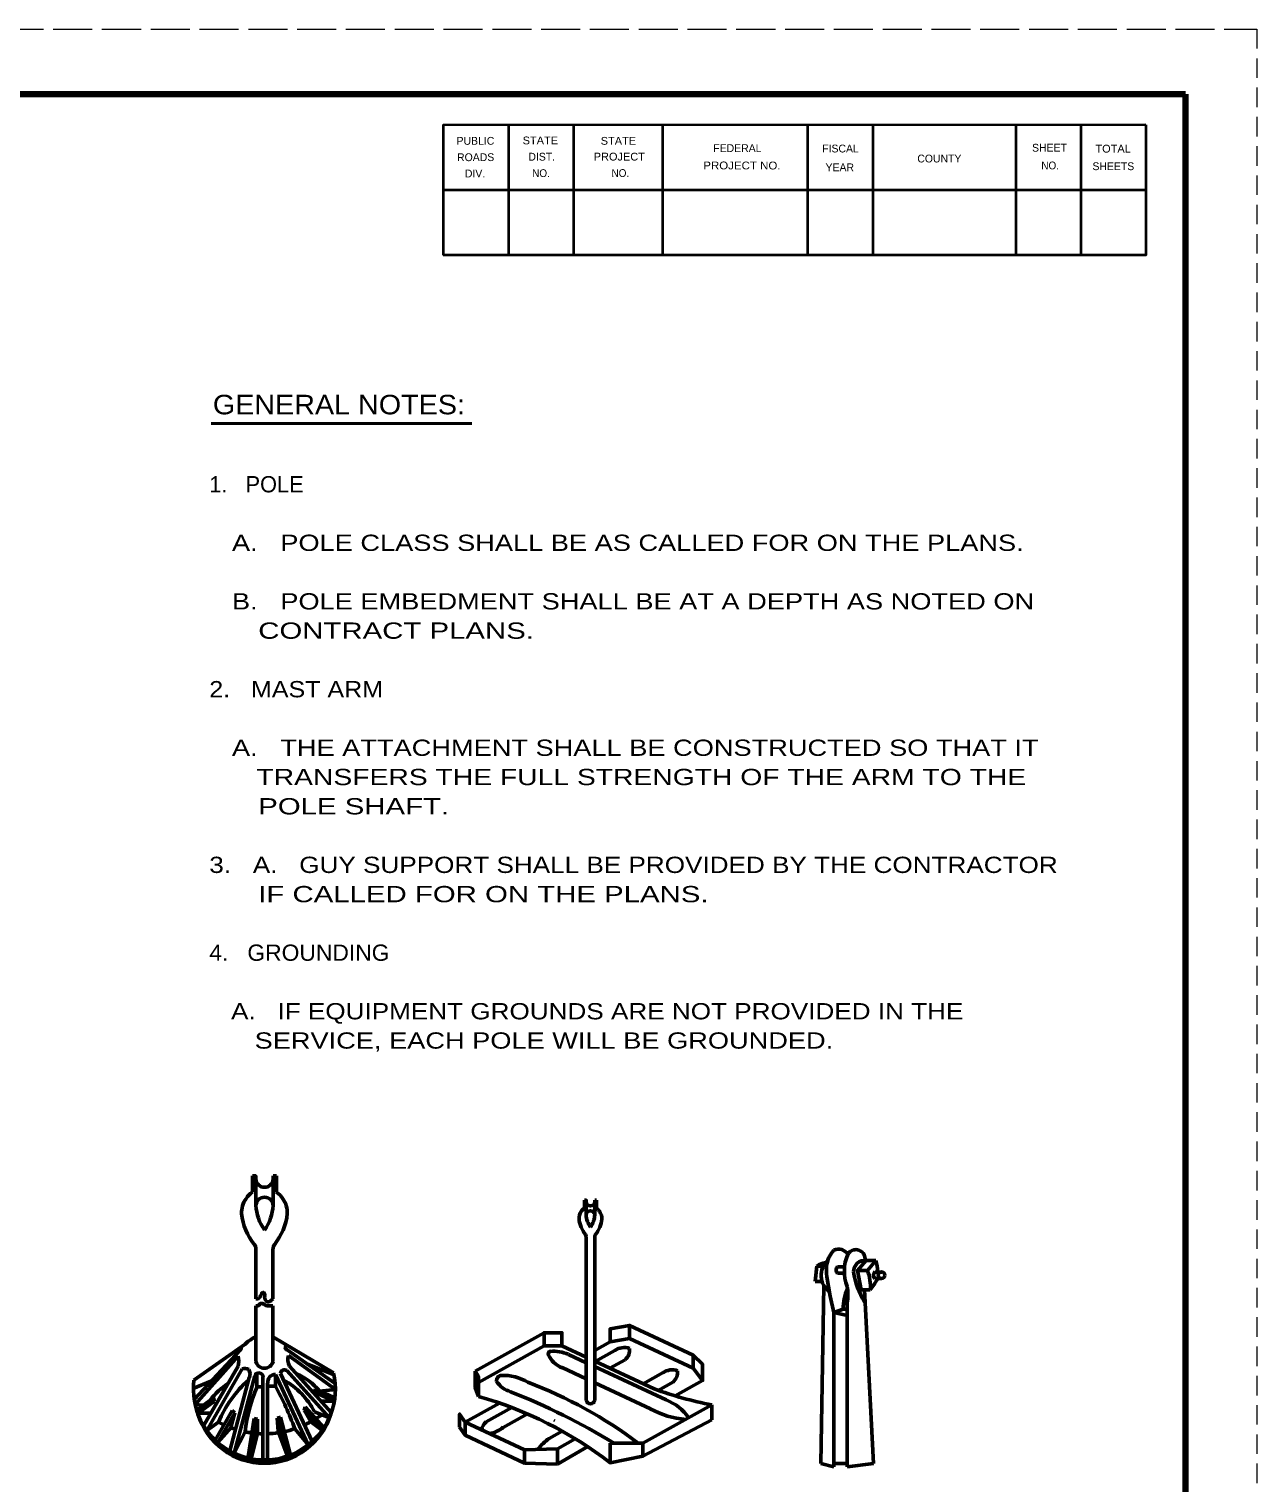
# Model space of a CAD drawing. Extents: x -1 to 679, y 0 to 440.
# Drawn here: x 490.2 to 678.9, y 216.8 to 440.2 of the extents above; entities that cross this region are included whole.
import ezdxf

# ---------------------------------------------------------------- set-up
doc = ezdxf.new("R2010")
doc.units = 0
doc.linetypes.add('LONG_DASHED', pattern=[7.5, 6, -1.5])
doc.linetypes.add('MEDIUM_DASHED', pattern=[4.5, 3, -1.5])
doc.layers.add('1', color=7, linetype='Continuous', lineweight=53)
doc.layers.add('61', color=7, linetype='Continuous', lineweight=35)

msp = doc.modelspace()

# ---------------------------------------------------------------- linework, layer by layer
at = {"layer": '1', "linetype": 'MEDIUM_DASHED', "lineweight": 13}
msp.add_line((678.891, 440.242), (678.871, 0.222), dxfattribs=at)
at = {"layer": '1', "lineweight": 40}
msp.add_line((518.16, 379.637), (558.213, 379.637), dxfattribs=at)
at = {"layer": '1'}
for p, q in [((524.516, 263.979), (524.516, 261.459)), ((527.676, 263.479), (527.676, 263.979)), ((527.676, 263.979), (528.176, 263.979)), ((528.176, 263.979), (528.176, 261.459)), ((525.016, 263.479), (525.016, 259.439)), ((527.676, 263.479), (527.676, 259.439)), ((575.536, 260.239), (575.536, 258.979)), ((575.796, 259.999), (575.796, 257.979)), ((577.116, 259.999), (577.116, 260.239)), ((577.116, 260.239), (577.376, 260.239)), ((577.116, 259.999), (577.116, 257.979)), ((577.376, 260.239), (577.376, 258.979)), ((525.016, 252.779), (525.016, 245.059)), ((527.656, 252.779), (527.656, 245.059)), ((575.796, 254.639), (575.796, 229.439)), ((577.116, 254.639), (577.116, 229.439)), ((611.236, 250.119), (610.996, 247.719)), ((612.256, 250.119), (611.236, 250.119)), ((615.516, 249.999), (614.416, 249.999)), ((615.436, 249.019), (614.416, 249.019)), ((621.216, 249.199), (620.196, 249.199)), ((621.216, 248.199), (620.196, 248.199)), ((611.996, 247.719), (610.996, 247.719)), ((611.856, 219.779), (612.336, 247.099)), ((618.556, 246.459), (618.056, 246.459)), ((619.956, 219.779), (618.556, 246.459)), ((618.556, 246.459), (619.456, 246.459)), ((525.016, 235.419), (525.016, 243.999)), ((527.656, 235.419), (527.656, 243.999)), ((615.896, 219.279), (615.896, 244.479)), ((613.876, 219.279), (613.876, 242.959)), ((613.876, 242.959), (615.896, 242.539)), ((527.636, 239.259), (536.956, 233.679)), ((569.316, 239.859), (558.736, 233.979)), ((582.436, 240.999), (592.256, 236.419)), ((523.376, 238.119), (515.496, 232.599)), ((522.656, 237.259), (515.536, 229.619)), ((529.836, 237.259), (537.216, 232.079)), ((569.316, 237.839), (559.236, 232.239)), ((572.076, 237.839), (575.776, 236.099)), ((579.456, 238.459), (577.116, 237.159)), ((580.196, 237.139), (577.176, 235.459)), ((579.456, 238.459), (582.436, 238.979)), ((582.436, 238.979), (592.256, 234.399)), ((522.296, 236.239), (515.676, 228.819)), ((522.296, 234.739), (516.996, 225.559)), ((530.016, 236.379), (537.256, 231.119)), ((530.196, 234.739), (536.616, 227.599)), ((536.956, 233.459), (532.976, 235.059)), ((573.056, 236.539), (575.796, 235.259)), ((577.096, 234.659), (588.076, 229.539)), ((577.116, 235.499), (586.236, 231.239)), ((581.796, 235.719), (579.436, 234.399)), ((592.256, 236.419), (592.256, 234.399)), ((522.936, 234.319), (517.476, 224.859)), ((524.016, 232.999), (520.996, 221.699)), ((524.876, 233.239), (521.676, 221.339)), ((525.196, 231.559), (525.196, 233.679)), ((526.116, 233.079), (526.116, 220.299)), ((528.056, 233.459), (533.076, 222.659)), ((528.816, 233.599), (533.696, 223.159)), ((529.796, 234.059), (536.316, 226.799)), ((572.096, 234.499), (575.796, 232.759)), ((587.636, 233.739), (584.536, 232.019)), ((515.396, 231.299), (518.116, 232.399)), ((525.196, 231.559), (526.116, 231.559)), ((526.836, 232.139), (526.836, 220.299)), ((534.156, 231.239), (537.016, 229.899)), ((534.156, 231.239), (534.176, 230.659)), ((534.176, 230.659), (536.996, 229.359)), ((537.256, 231.119), (534.856, 230.899)), ((577.116, 232.159), (585.656, 228.179)), ((589.196, 232.299), (586.856, 230.999)), ((515.676, 228.819), (516.916, 228.719)), ((515.836, 227.919), (518.496, 229.839)), ((516.136, 227.519), (518.656, 229.339)), ((518.496, 229.839), (518.656, 229.339)), ((532.616, 228.479), (532.436, 227.939)), ((532.436, 227.939), (535.096, 224.959)), ((533.456, 226.179), (532.436, 227.939)), ((532.616, 228.479), (535.476, 225.299)), ((536.996, 229.359), (535.036, 229.359)), ((564.376, 228.359), (560.396, 226.159)), ((595.096, 228.759), (595.096, 226.499)), ((516.136, 227.519), (518.176, 227.519)), ((517.476, 224.859), (519.296, 226.139)), ((518.776, 223.339), (521.396, 227.899)), ((519.156, 222.999), (521.776, 227.559)), ((521.776, 227.559), (521.196, 225.319)), ((521.396, 227.899), (521.776, 227.559)), ((524.776, 226.679), (523.836, 220.779)), ((525.256, 226.599), (524.336, 220.699)), ((524.776, 226.679), (525.256, 226.599)), ((525.256, 226.599), (525.256, 224.359)), ((528.796, 226.899), (528.296, 226.759)), ((528.296, 226.759), (529.836, 221.059)), ((528.296, 226.759), (528.476, 224.719)), ((528.796, 226.899), (530.296, 221.259)), ((535.096, 224.959), (533.456, 226.179)), ((536.316, 226.799), (534.056, 227.699)), ((557.196, 226.119), (566.336, 221.859)), ((557.196, 226.119), (557.196, 224.099)), ((566.756, 227.379), (563.056, 225.319)), ((519.156, 222.999), (521.216, 225.299)), ((521.676, 221.339), (523.356, 224.639)), ((524.336, 220.699), (525.256, 224.359)), ((529.836, 221.059), (528.476, 224.719)), ((533.076, 222.659), (531.016, 225.099)), ((572.096, 224.739), (570.116, 223.599)), ((574.096, 223.579), (571.396, 222.019)), ((566.336, 221.859), (571.376, 222.039)), ((566.336, 221.859), (566.336, 219.839)), ((576.056, 222.379), (571.376, 219.659)), ((571.376, 222.039), (571.376, 219.659)), ((584.516, 222.899), (584.516, 220.879)), ((566.336, 219.839), (571.376, 219.659)), ((611.856, 219.779), (613.876, 219.279)), ((613.876, 219.779), (615.896, 219.779)), ((615.896, 219.279), (619.956, 219.779))]:
    msp.add_line(p, q, dxfattribs=at)
at = {"layer": '1', "lineweight": 13}
for p, q in [((589.496, 230.159), (589.316, 230.059)), ((570.816, 226.219), (571.016, 226.559))]:
    msp.add_line(p, q, dxfattribs=at)
at = {"layer": '1'}
for points in [[(525.016, 263.479), (525.016, 263.979), (524.516, 263.979)], [(575.796, 259.999), (575.796, 260.239), (575.536, 260.239)], [(618.056, 246.459), (617.516, 249.439), (619.036, 249.439), (620.336, 250.979)], [(617.516, 249.439), (618.816, 250.979), (620.336, 250.979)], [(613.876, 242.959), (613.316, 245.479), (612.796, 248.459)], [(613.876, 242.959), (615.296, 243.479), (615.896, 243.479)], [(579.456, 238.459), (579.456, 240.459), (582.436, 240.999), (582.436, 238.979)], [(592.256, 235.999), (592.256, 236.419), (593.696, 235.019), (593.696, 232.499)], [(528.056, 233.459), (528.056, 231.639), (526.836, 231.639)], [(558.736, 233.979), (559.236, 233.119), (559.236, 230.079)], [(558.736, 233.979), (558.736, 231.459), (559.236, 230.079)], [(592.256, 234.399), (593.696, 232.499), (589.496, 230.159)], [(562.496, 229.059), (557.196, 226.119), (556.336, 227.359), (556.336, 225.339)], [(595.096, 228.759), (584.516, 222.899), (579.476, 222.899)], [(579.476, 222.899), (579.476, 219.879), (584.516, 220.879), (595.096, 226.499)], [(556.336, 225.339), (557.196, 224.099), (566.336, 219.839)]]:
    msp.add_lwpolyline(points, dxfattribs=at)
msp.add_lwpolyline([(572.076, 237.839), (572.076, 239.859), (569.316, 239.859), (569.316, 237.839)], close=True, dxfattribs=at)
msp.add_circle((621.191, 248.704), 0.504, dxfattribs=at)
for centre, radius, start, end in [((525.793, 259.176), 2.616, 119.19068, 150.80932), ((526.351, 263.548), 1.332, 183.14868, 356.60343), ((526.886, 259.176), 2.616, 29.19068, 60.80932), ((526.509, 258.307), 3.688, 144.42176, 182.06662), ((526.351, 259.364), 1.332, 3.15687, 176.59703), ((532.291, 259.869), 7.282, 183.35766, 215.34932), ((520.412, 259.864), 7.282, 324.65068, 356.64234), ((526.171, 258.307), 3.688, 357.93338, 35.57824), ((576.455, 260.031), 0.666, 183.14868, 356.60343), ((532.175, 259.25), 9.414, 186.56595, 218.44896), ((520.505, 259.25), 9.414, 321.55104, 353.43405), ((576.534, 257.41), 1.844, 144.42176, 182.06662), ((579.367, 257.882), 4.707, 186.56595, 218.44896), ((576.176, 257.845), 1.308, 119.19068, 150.80932), ((576.455, 257.939), 0.666, 3.15687, 176.59703), ((579.425, 258.192), 3.641, 183.35766, 215.34932), ((573.485, 258.189), 3.641, 324.65068, 356.64234), ((573.532, 257.882), 4.707, 321.55104, 353.43405), ((576.722, 257.845), 1.308, 29.19068, 60.80932), ((576.365, 257.41), 1.844, 357.93338, 35.57824), ((575.286, 254.642), 0.504, 0, 38.44896), ((577.612, 254.642), 0.504, 141.55104, 180), ((524.014, 252.77), 1.008, 0, 38.44896), ((528.666, 252.77), 1.008, 141.55104, 180), ((617.02, 249.568), 4.325, 136.6517, 167.95246), ((614.601, 251.124), 1.588, 27.27122, 117.20122), ((617.252, 251.212), 1.423, 354.19595, 131.52888), ((613.133, 247.234), 3.446, 98.89517, 123.27294), ((614.931, 248.656), 3.032, 130.0252, 235.18403), ((622.401, 249.463), 9.664, 174.01262, 185.98737), ((622.061, 249.306), 6.589, 156.78247, 200.56684), ((619.515, 249.365), 4.332, 137.75004, 144.12043), ((618.637, 249.241), 1.744, 84.04734, 179.89391), ((614.978, 249.361), 5.59, 358.55245, 16.7912), ((614.89, 249.511), 0.671, 133.97941, 226.02058), ((628.805, 250.931), 12.03, 188.05699, 211.90806), ((612.645, 246.995), 6.838, 355.44941, 20.86555), ((612.251, 252.251), 9.252, 321.19678, 333.99968), ((620.559, 248.699), 0.618, 125.33791, 234.66209), ((623.717, 243.391), 8.422, 157.16459, 179.40955), ((610.27, 245.733), 5.76, 347.36391, 12.63609), ((528.106, 233.103), 6.892, 116.58954, 133.41014), ((522.609, 237.411), 0.167, 285.47106, 119.84894), ((529.834, 237.548), 0.298, 72.34222, 272.05741), ((570.341, 236.624), 0.386, 85.12517, 207.35251), ((570.706, 230.949), 6.071, 67.29002, 93.88305), ((581.638, 235.092), 2.502, 70.73362, 125.44724), ((580.396, 237.257), 2.077, 312.2199, 5.43688), ((519.368, 235.486), 3.028, 345.54353, 14.45647), ((526.34, 235.785), 1.368, 195.24731, 344.75269), ((532.305, 235.796), 2.362, 165.83192, 206.84011), ((573.544, 238.143), 3.929, 204.55458, 248.28903), ((526.334, 231.225), 10.92, 172.76636, 12.86069), ((535.571, 219.45), 17.588, 131.72438, 157.64771), ((523.291, 232.954), 1.417, 63.18198, 104.27978), ((522.796, 233.516), 1.334, 336.72582, 31.75765), ((525.483, 233.051), 0.64, 2.53809, 163.55027), ((528.028, 232.26), 1.196, 89.05434, 186.28866), ((529.433, 233.544), 0.621, 54.79805, 174.78973), ((523.671, 222.377), 11.659, 27.13242, 61.23505), ((526.2, 223.113), 11.652, 41.97741, 64.76098), ((562.821, 232.507), 0.804, 94.88611, 188.90189), ((563.034, 225.968), 7.345, 59.08543, 92.19679), ((589.017, 231.665), 2.502, 70.73362, 125.44724), ((587.775, 233.83), 2.077, 312.2199, 5.43688), ((526.823, 222.711), 11.153, 122.96526, 142.37873), ((551.034, 220.963), 27.92, 157.68458, 172.42454), ((482.668, 207.115), 51.58, 20.41201, 28.38414), ((565.204, 234.448), 3.79, 213.03543, 254.05828), ((525.168, 132.459), 105.794, 58.74865, 68.37109), ((542.249, 167.701), 69.082, 53.04115, 69.17556), ((606.818, 288.061), 60.44, 250.09888, 258.8259), ((542.438, 171.585), 60.867, 52.50633, 73.9788), ((576.449, 229.621), 0.683, 195.19877, 344.80123), ((592.153, 239.974), 13.477, 241.1379, 265.46719), ((585.415, 222.67), 7.369, 33.93256, 68.86981), ((526.334, 230.48), 10.679, 196.98242, 343.01758), ((526.334, 238.953), 14.616, 241.25089, 244.7288), ((526.334, 238.953), 14.616, 294.68825, 298.86032), ((526.334, 238.953), 14.616, 302.79246, 306.95206), ((561.815, 224.509), 2.176, 130.48502, 167.67788), ((526.334, 238.953), 14.616, 249.43644, 252.21677), ((526.334, 238.953), 14.616, 258.07352, 262.19692), ((526.334, 238.953), 14.616, 265.78587, 269.16942), ((526.334, 238.953), 14.616, 271.8867, 278.3643), ((526.334, 238.953), 14.616, 282.12514, 288.50814), ((559.861, 229.343), 5.13, 282.65039, 308.50672), ((572.968, 218.907), 5.489, 121.25992, 146.56057)]:
    msp.add_arc(centre, radius, start, end, dxfattribs=at)
for points in [[(525.016, 245.059), (525.456, 245.139), (525.716, 245.519), (525.976, 245.959), (526.236, 246.039), (526.376, 245.619), (526.376, 245.259), (526.496, 244.919), (526.756, 244.619), (527.156, 244.659), (527.536, 244.999), (527.656, 245.059)], [(525.016, 243.999), (525.296, 243.999), (525.496, 244.099), (525.676, 244.339), (525.876, 244.379), (526.196, 244.299), (526.376, 244.139), (526.796, 243.999), (527.116, 243.999), (527.656, 243.999)]]:
    msp.add_spline(points, degree=3, dxfattribs=at)
at = {"layer": '61', "linetype": 'LONG_DASHED', "lineweight": 13}
msp.add_line((-1.129, 440.242), (678.891, 440.242), dxfattribs=at)
at = {"layer": '61', "lineweight": 158}
msp.add_line((667.911, 430.242), (667.931, 10.202), dxfattribs=at)
at = {"layer": '61'}
for p, q in [((563.831, 425.482), (563.831, 405.482)), ((573.831, 425.482), (573.831, 405.482)), ((587.511, 425.482), (587.511, 405.482)), ((609.831, 425.482), (609.831, 405.482)), ((619.831, 425.482), (619.831, 405.482)), ((641.811, 425.502), (641.811, 405.502)), ((651.811, 425.502), (651.811, 405.502)), ((661.831, 415.462), (553.811, 415.482))]:
    msp.add_line(p, q, dxfattribs=at)
at = {"layer": '61', "lineweight": 158}
msp.add_lwpolyline([(667.911, 430.242), (28.871, 430.242), (28.871, 10.222)], dxfattribs=at)
at = {"layer": '61'}
for points in [[(661.811, 425.502), (553.831, 425.482), (553.831, 405.482)], [(661.811, 425.502), (661.811, 405.502), (553.831, 405.482)]]:
    msp.add_lwpolyline(points, dxfattribs=at)

# ---------------------------------------------------------------- texts
at = {"layer": '1'}
for s, height, width, p in [('GENERAL NOTES:', 3, 1.1, (518.414, 381.027)), ('   A.   POLE CLASS SHALL BE AS CALLED FOR ON THE PLANS.', 2.5, 1.25, (517.865, 360.032)), ('   B.   POLE EMBEDMENT SHALL BE AT A DEPTH AS NOTED ON', 2.5, 1.25, (517.865, 351.032)), ('      CONTRACT PLANS.', 2.5, 1.35, (517.865, 346.532)), ('2.   MAST ARM', 2.5, 1.15, (517.865, 337.532)), ('   A.   THE ATTACHMENT SHALL BE CONSTRUCTED SO THAT IT', 2.5, 1.25, (517.865, 328.532)), ('      TRANSFERS THE FULL STRENGTH OF THE ARM TO THE', 2.5, 1.3, (517.865, 324.032)), ('      POLE SHAFT.', 2.5, 1.35, (517.865, 319.532)), ('3.   A.   GUY SUPPORT SHALL BE PROVIDED BY THE CONTRACTOR', 2.5, 1.2, (517.865, 310.532)), ('      IF CALLED FOR ON THE PLANS.', 2.5, 1.35, (517.865, 306.032)), ('4.   GROUNDING', 2.5, 1.05, (517.865, 297.032)), ('   A.   IF EQUIPMENT GROUNDS ARE NOT PROVIDED IN THE', 2.5, 1.2, (517.865, 288.032)), ('      SERVICE, EACH POLE WILL BE GROUNDED.', 2.5, 1.25, (517.865, 283.532))]:
    msp.add_text(s, height=height, dxfattribs=dict(at, width=width)).set_placement(p)
msp.add_text('1.   POLE', height=2.5, dxfattribs=at).set_placement((517.865, 369.032))
at = {"layer": '61'}
for s, rotation, p in [('PUBLIC', 0.033, (555.871, 422.462)), ('FEDERAL', 0.007, (595.331, 421.342)), ('FISCAL', 359.942, (612.071, 421.282)), ('SHEET', 0.059, (644.331, 421.402)), ('ROADS', 0.124, (555.951, 419.942)), ('DIST.', 0.056, (566.911, 420.022)), ('COUNTY', 0.069, (626.691, 419.742)), ('DIV.', 359.932, (557.151, 417.442)), ('YEAR', 0.105, (612.591, 418.382)), ('SHEETS', 359.959, (653.611, 418.562))]:
    msp.add_text(s, height=1.201, rotation=rotation, dxfattribs=at).set_placement(p)
for s, rotation, width, p in [('STATE', 0.059, 1.05, (566.031, 422.522)), ('STATE', 0.059, 1.05, (578.031, 422.462)), ('TOTAL', 359.926, 1.05, (654.071, 421.262)), ('PROJECT', 359.908, 1.05, (576.951, 420.042)), ('NO.', 359.852, 0.95, (567.491, 417.502)), ('NO.', 0.225, 0.95, (579.691, 417.502)), ('PROJECT NO.', 359.922, 1.1, (593.791, 418.682)), ('NO.', 359.852, 0.95, (645.751, 418.682))]:
    msp.add_text(s, height=1.201, rotation=rotation, dxfattribs=dict(at, width=width)).set_placement(p)

doc.saveas('drawing.dxf')
